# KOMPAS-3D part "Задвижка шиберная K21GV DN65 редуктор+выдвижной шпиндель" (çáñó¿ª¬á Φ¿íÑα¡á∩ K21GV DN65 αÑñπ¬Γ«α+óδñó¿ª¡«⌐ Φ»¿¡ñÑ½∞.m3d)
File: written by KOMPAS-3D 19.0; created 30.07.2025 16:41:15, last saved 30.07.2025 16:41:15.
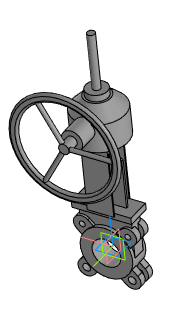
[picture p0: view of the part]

Document properties: Полное имя файла: Задвижка шиберная K21GV DN65 редуктор+выдвижной шпиндель.a3d

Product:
- Part/product: Задвижка шиберная K21GV DN65 редуктор+выдвижной шпиндель
    Масса: 17.3635

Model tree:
1. Операция без истории:1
